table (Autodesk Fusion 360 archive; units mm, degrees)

design "millingcoffeetablefabacd" references "cutting final cnc stool faba acd"
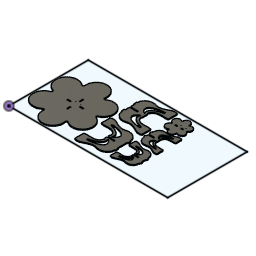
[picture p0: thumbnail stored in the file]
parameter "thickness" = 12 comment "plywood thickness"
parameter "slot1" = 13 comment "sloth dimentione"
parameter "slot2" = 13.2 comment "slot 1"
sketch "shape flower 1meter" plane through (0, 0, 0) normal (0, 0, 1) x axis (1, 0, 0)
  curve K1 (-39.7573, -29.352) -> (-39.7821, -29.352)
  curve K2 (-39.7821, -29.3556) -> (-39.7573, -29.352)
  line L1 (-39.7821, -29.352) -> (-39.7821, -29.3556)
  line L2 (-35.9332, 49.8113) -> (-35.9332, 49.8077)
  curve K3 (-35.838, 49.7971) -> (-35.9332, 49.8113)
  line L3 (308.597, -188.8388) -> (308.8105, -188.7105)
  curve K4 (23.8593, -355.0901) -> (308.597, -188.8388)
  line L4 (23.845, -355.1043) -> (23.8593, -355.0901)
  curve K5 (-14.6061, -354.7911) -> (23.845, -355.1043)
  curve K6 (-303.7587, -199.6903) -> (-14.6061, -354.7911)
  curve K7 (-303.7444, -199.6761) -> (-303.7587, -199.6903)
  curve K8 (-321.3466, -169.9122) -> (-303.7444, -199.6761)
  curve K9 (-329.7916, -170.4675) -> (-329.6918, -170.4675)
  curve K10 (-314.2542, 149.1041) -> (-329.7916, -170.4675)
  line L5 (-314.2542, 149.0898) -> (-314.2542, 149.1041)
  curve K11 (-311.2495, 148.6625) -> (-313.87, 149.047)
  curve K12 (-288.948, 178.2557) -> (-311.2495, 148.6625)
  curve K13 (-18.4511, 342.0005) -> (-288.948, 178.2557)
  line L6 (-18.4226, 342.0148) -> (-18.4511, 342.0005)
  curve K14 (20.242, 342.2854) -> (-18.4226, 342.0148)
  curve K15 (20.2705, 342.328) -> (20.242, 342.2854)
  curve K16 (293.5297, 185.9602) -> (20.2705, 342.328)
  curve K17 (293.5155, 185.9317) -> (293.5297, 185.9602)
  curve K18 (312.9976, 157.4779) -> (293.5155, 185.9317)
  curve K19 (323.3506, -159.9576) -> (312.9976, 157.4779)
  curve K20 (308.8105, -188.7105) -> (323.3506, -159.9576)
  curve K21 (-39.7573, -29.352) -> (-37.6901, -29.2145)
  closed curve K22 centre (-35.8975, 48.3404)
  closed curve K23 centre (-375.539, -219.5003)
  closed curve K24 centre (-314.1102, 143.1665)
  closed curve K25 centre (-51.1145, -41.4983)
extrude "Extrude1" new body sketch "shape flower 1meter" along normal blind 12 (= "thickness") bodies "top"
sketch "legs fab acd 1 meter 46 height" plane through (0, 0, 0) normal (0, 0, 1) x axis (1, 0, 0)
  line L1 (-32.825, -144.3201) -> (34.9534, -144.3201)
  curve K1 (37.0389, -82.2767) -> (-32.825, -144.3201)
  curve K2 (34.9534, -144.3201) -> (37.0389, -82.2767)
  line L2 (-58.3723, -144.3201) -> (-80.7913, -144.3201)
  curve K3 (3.6711, -91.1401) -> (-58.3723, -144.3201)
  curve K4 (-27.6113, -47.3448) -> (3.6711, -91.1401)
  curve K5 (-80.7913, -144.3201) -> (-27.6113, -47.3448)
  curve K6 (79.9971, 179.4525) -> (161.3312, 145.0418)
  curve K7 (132.6558, 269.1286) -> (79.9971, 179.4525)
  line L3 (161.3312, 269.1286) -> (132.6558, 269.1286)
  line L4 (161.3312, 145.0418) -> (161.3312, 269.1286)
  curve K8 (71.9709, 176.8456) -> (-2.064, 83.6941)
  curve K9 (1.5856, 233.6752) -> (71.9709, 176.8456)
  curve K10 (-17.1838, 141.3922) -> (1.5856, 233.6752)
  curve K11 (-2.064, 83.6941) -> (-17.1838, 141.3922)
  curve K12 (47.0854, 262.3992) -> (10.0679, 247.2794)
  line L5 (100.7868, 262.3992) -> (47.0854, 262.3992)
  curve K13 (60.6411, 205.0482) -> (100.7868, 262.3992)
  curve K14 (10.0679, 247.2794) -> (60.6411, 205.0482)
  curve K15 (68.4743, 9.5654) -> (135.0093, 68.3558)
  curve K16 (59.9335, -29.5908) -> (68.4743, 9.5654)
  curve K17 (59.9335, -97.1977) -> (59.9335, -29.5908)
  curve K18 (58.79, -141.8164) -> (59.9335, -97.1977)
  line L6 (58.7898, -141.8113) -> (58.79, -141.8164)
  line L7 (55.6808, -167.4134) -> (58.7898, -141.8113)
  line L8 (-83.214, -167.4134) -> (55.6808, -167.4134)
  curve K19 (-87.1704, -96.1666) -> (-83.214, -167.4134)
  curve K20 (-49.2854, -14.2704) -> (-87.1704, -96.1666)
  curve K21 (-27.4151, 77.7135) -> (-49.2854, -14.2704)
  curve K22 (-30.7897, 102.6214) -> (-27.4151, 77.7135)
  curve K23 (-39.8563, 135.5953) -> (-30.7897, 102.6214)
  curve K24 (11.8482, 271.9936) -> (-39.8563, 135.5953)
  curve K25 (46.7469, 288.6515) -> (11.8482, 271.9936)
  line L9 (195.8212, 288.6515) -> (46.7469, 288.6515)
  line L10 (195.8212, 263.8152) -> (195.8212, 288.6515)
  curve K26 (195.7345, 75.4724) -> (195.8212, 263.8152)
  line L11 (195.7345, 58.9478) -> (195.7345, 75.4724)
  line L12 (147.9989, 58.9478) -> (195.7345, 58.9478)
  curve K27 (135.0093, 68.3558) -> (147.9989, 58.9478)
  curve K28 (-5.7438, -51.5785) -> (-5.8152, -30.5557)
  curve K29 (9.3316, -62.4779) -> (-5.7438, -51.5785)
  curve K30 (18.7965, -36.6002) -> (9.3316, -62.4779)
  curve K31 (43.1071, 29.9194) -> (18.7965, -36.6002)
  curve K32 (81.3903, 84.1408) -> (43.1071, 29.9194)
  curve K33 (161.3312, 92.9063) -> (81.3903, 84.1408)
  curve K34 (86.4903, 153.0394) -> (161.3312, 92.9063)
  curve K35 (-5.8152, -30.5506) -> (86.4903, 153.0394)
  line L13 (-5.8152, -30.5557) -> (-5.8152, -30.5506)
  line L14 (68.2014, 288.6515) -> (118.2014, 288.6515)
  line L15 (68.2014, 300.6515) -> (68.2014, 288.6515)
  line L16 (118.2014, 300.6515) -> (68.2014, 300.6515)
  line L17 (118.2014, 288.6515) -> (118.2014, 300.6515)
  point P50 (118.2014, 288.6515)
  point P51 (68.2014, 288.6515)
  point P52 (68.2014, 300.6515)
  point P53 (118.2014, 300.6515)
  horizontal L14
  vertical L15
  horizontal L16
  vertical L17
  coincident L9 P50
  dimension "d16" distance P51 P52 = 12
  dimension "d17" distance P52 P53 = 50
extrude "Extrude3" new body sketch "legs fab acd 1 meter 46 height" along normal blind 12 (= "thickness") bodies "old legs (1)"
move "Move2"
mirror "Mirror2" mirrorStitchTolerance 0.1
sketch "Sketch4" plane through (0, 8.4468, 0) normal (0, 1, 0) x axis (-1, 0, 0)
  line L1 (-195.8152, -319.9974) -> (-195.8152, -320.0025)
  curve K1 (-103.5097, -136.4075) -> (-195.8152, -319.9974)
  curve K2 (-28.6688, -196.5406) -> (-103.5097, -136.4075)
  curve K3 (-108.6097, -205.3061) -> (-28.6688, -196.5406)
  curve K4 (-146.8929, -259.5274) -> (-108.6097, -205.3061)
  curve K5 (-171.2035, -326.047) -> (-146.8929, -259.5274)
  curve K6 (-180.6684, -351.9248) -> (-171.2035, -326.047)
  curve K7 (-195.7438, -341.0254) -> (-180.6684, -351.9248)
  curve K8 (-195.8152, -320.0025) -> (-195.7438, -341.0254)
  line L2 (-71.7986, -0.7953) -> (71.7986, -0.7953)
  line L3 (-71.7986, 11.2047) -> (-71.7986, -0.7953)
  line L4 (-121.7986, 11.2047) -> (-71.7986, 11.2047)
  line L5 (-121.7986, -0.7953) -> (-121.7986, 11.2047)
  line L6 (-143.2531, -0.7953) -> (-121.7986, -0.7953)
  curve K9 (-143.2531, -0.7953) -> (-178.1518, -17.4533)
  curve K10 (-178.1518, -17.4533) -> (-229.8563, -153.8516)
  curve K11 (-229.8563, -153.8516) -> (-220.7897, -186.8255)
  curve K12 (-220.7897, -186.8255) -> (-217.4151, -211.7333)
  curve K13 (-217.4151, -211.7333) -> (-239.2854, -303.7172)
  curve K14 (-239.2854, -303.7172) -> (-277.1704, -385.6134)
  curve K15 (-277.1704, -385.6134) -> (-273.214, -456.8603)
  line L7 (-134.3192, -456.8603) -> (-273.214, -456.8603)
  line L8 (-131.2102, -431.2581) -> (-134.3192, -456.8603)
  line L9 (-131.21, -431.2633) -> (-131.2102, -431.2581)
  curve K16 (-131.21, -431.2633) -> (-130.0665, -386.6446)
  curve K17 (-130.0665, -386.6446) -> (-130.0665, -319.0377)
  curve K18 (-130.0665, -319.0377) -> (-121.5257, -279.8815)
  curve K19 (-121.5257, -279.8815) -> (-54.9907, -221.091)
  curve K20 (-54.9907, -221.091) -> (-42.0011, -230.4991)
  line L10 (42.0011, -230.4991) -> (-42.0011, -230.4991)
  curve K21 (54.9907, -221.091) -> (42.0011, -230.4991)
  curve K22 (121.5257, -279.8815) -> (54.9907, -221.091)
  curve K23 (130.0665, -319.0377) -> (121.5257, -279.8815)
  curve K24 (130.0665, -386.6446) -> (130.0665, -319.0377)
  curve K25 (131.21, -431.2633) -> (130.0665, -386.6446)
  line L11 (131.2102, -431.2581) -> (131.21, -431.2633)
  line L12 (134.3192, -456.8603) -> (131.2102, -431.2581)
  line L13 (273.214, -456.8603) -> (134.3192, -456.8603)
  curve K26 (277.1704, -385.6134) -> (273.214, -456.8603)
  curve K27 (239.2854, -303.7172) -> (277.1704, -385.6134)
  curve K28 (217.4151, -211.7333) -> (239.2854, -303.7172)
  curve K29 (220.7897, -186.8255) -> (217.4151, -211.7333)
  curve K30 (229.8563, -153.8516) -> (220.7897, -186.8255)
  curve K31 (178.1518, -17.4533) -> (229.8563, -153.8516)
  curve K32 (143.2531, -0.7953) -> (178.1518, -17.4533)
  line L14 (121.7986, -0.7953) -> (143.2531, -0.7953)
  line L15 (121.7986, 11.2047) -> (121.7986, -0.7953)
  line L16 (71.7986, 11.2047) -> (121.7986, 11.2047)
  line L17 (71.7986, -0.7953) -> (71.7986, 11.2047)
  line L18 (195.8152, -320.0025) -> (195.8152, -319.9974)
  curve K33 (195.8152, -320.0025) -> (195.7438, -341.0254)
  curve K34 (195.7438, -341.0254) -> (180.6684, -351.9248)
  curve K35 (180.6684, -351.9248) -> (171.2035, -326.047)
  curve K36 (171.2035, -326.047) -> (146.8929, -259.5274)
  curve K37 (146.8929, -259.5274) -> (108.6097, -205.3061)
  curve K38 (108.6097, -205.3061) -> (28.6688, -196.5406)
  curve K39 (28.6688, -196.5406) -> (103.5097, -136.4075)
  curve K40 (103.5097, -136.4075) -> (195.8152, -319.9974)
  line L19 (6.5, 0) -> (-6.5, 0)
  line L20 (6.5, -120) -> (6.5, 0)
  line L21 (-6.5, -120) -> (6.5, -120)
  line L22 (-6.5, 0) -> (-6.5, -120)
  point P1 (0, 0)
  point P60 (-6.5, 0)
  point P63 (-6.5, -120)
  point P62 (6.5, -120)
  horizontal L19
  vertical L20
  horizontal L21
  vertical L22
  midpoint P1 L19
  dimension "d18" distance P60 P63 = 120
  dimension "d70" distance P62 P63 = 13 (= "slot1")
copy_paste_bodies "CopyPasteBodies2"
move "Move4"
extrude "Extrude4" cut sketch "Sketch4" profile of L2 L20 L21 L22 against normal blind 75
chamfer "Chamfer1" distance 6.5 (= "slot1 / 2")
sketch "legs fab acd" plane through (0, 0, 0) normal (0, 0, 1) x axis (1, 0, 0)
  curve K1 (-42.4639, -297.829) -> (-43.2542, -328.6618)
  curve K2 (-42.4639, -251.1107) -> (-42.4639, -297.829)
  curve K3 (-36.562, -224.0526) -> (-42.4639, -251.1107)
  curve K4 (9.4156, -183.4267) -> (-36.562, -224.0526)
  curve K5 (51.4384, -48.3587) -> (51.3785, -178.509)
  curve K6 (-75.6922, -42.7072) -> (-51.5763, -31.196)
  curve K7 (-111.4216, -136.9623) -> (-75.6922, -42.7072)
  curve K8 (-105.1562, -159.7482) -> (-111.4216, -136.9623)
  curve K9 (-102.8243, -176.9603) -> (-105.1562, -159.7482)
  curve K10 (-117.9374, -240.5238) -> (-102.8243, -176.9603)
  curve K11 (-144.117, -297.1164) -> (-117.9374, -240.5238)
  curve K12 (-141.383, -346.3501) -> (-144.117, -297.1164)
  line L1 (-45.4027, -346.3501) -> (-141.383, -346.3501)
  line L2 (-43.2543, -328.6582) -> (-45.4027, -346.3501)
  line L3 (-43.2542, -328.6618) -> (-43.2543, -328.6582)
  curve K13 (-87.8489, -266.3048) -> (-87.8982, -251.7774)
  curve K14 (-77.4313, -273.8366) -> (-87.8489, -266.3048)
  curve K15 (-70.8908, -255.9543) -> (-77.4313, -273.8366)
  curve K16 (-54.0915, -209.9874) -> (-70.8908, -255.9543)
  curve K17 (-27.6367, -172.5189) -> (-54.0915, -209.9874)
  curve K18 (27.6048, -166.4616) -> (-27.6367, -172.5189)
  curve K19 (-24.1124, -124.9079) -> (27.6048, -166.4616)
  curve K20 (-87.8982, -251.7739) -> (-24.1124, -124.9079)
  line L4 (-87.8982, -251.7774) -> (-87.8982, -251.7739)
  line L5 (51.344, -30.0127) -> (51.4384, -48.3587)
  line L6 (27.6251, -185.9832) -> (37.3593, -185.9832)
  curve K21 (27.6251, -185.9832) -> (9.4156, -183.4267)
  line L7 (51.3785, -186.0408) -> (51.3785, -178.509)
  line L8 (51.3785, -186.0408) -> (37.3593, -185.9832)
  line L9 (-45, -30.0127) -> (51.344, -30.0127)
  line L10 (-33.6745, -30.0127) -> (22.2673, -30.0127)
  line L11 (-33.6745, -18.0127) -> (-33.6745, -30.0127)
  line L12 (22.2673, -18.0127) -> (-33.6745, -18.0127)
  line L13 (22.2673, -30.0127) -> (22.2673, -18.0127)
  curve K22 (-45, -30.0127) -> (-51.5763, -31.196)
  point P34 (22.2673, -30.0127)
  point P35 (-33.6745, -30.0127)
  point P36 (-33.6745, -18.0127)
  horizontal L6
  vertical L7
  horizontal L9
  horizontal L10
  vertical L11
  horizontal L12
  vertical L13
  coincident L9 P34
  dimension "d8" distance P35 P36 = 12
sketch "Sketch5" plane through (6, 0, 0) normal (1, 0, 0) x axis (0, 1, 0)
  line L1 (-193.3684, -319.9974) -> (-193.3684, -320.0025)
  curve K1 (-101.0629, -136.4075) -> (-193.3684, -319.9974)
  curve K2 (-26.2219, -196.5406) -> (-101.0629, -136.4075)
  curve K3 (-106.1629, -205.3061) -> (-26.2219, -196.5406)
  curve K4 (-144.4461, -259.5274) -> (-106.1629, -205.3061)
  curve K5 (-168.7567, -326.047) -> (-144.4461, -259.5274)
  curve K6 (-178.2216, -351.9248) -> (-168.7567, -326.047)
  curve K7 (-193.297, -341.0254) -> (-178.2216, -351.9248)
  curve K8 (-193.3684, -320.0025) -> (-193.297, -341.0254)
  line L2 (-69.3517, -0.7953) -> (74.2454, -0.7953)
  line L3 (-69.3517, 11.2047) -> (-69.3517, -0.7953)
  line L4 (-119.3517, 11.2047) -> (-69.3517, 11.2047)
  line L5 (-119.3517, -0.7953) -> (-119.3517, 11.2047)
  line L6 (-140.8063, -0.7953) -> (-119.3517, -0.7953)
  curve K9 (-140.8063, -0.7953) -> (-175.7049, -17.4533)
  curve K10 (-175.7049, -17.4533) -> (-227.4094, -153.8516)
  curve K11 (-227.4094, -153.8516) -> (-218.3428, -186.8255)
  curve K12 (-218.3428, -186.8255) -> (-214.9682, -211.7333)
  curve K13 (-214.9682, -211.7333) -> (-236.8386, -303.7172)
  curve K14 (-236.8386, -303.7172) -> (-274.7236, -385.6134)
  curve K15 (-274.7236, -385.6134) -> (-270.7672, -456.8603)
  line L7 (-131.8724, -456.8603) -> (-270.7672, -456.8603)
  line L8 (-128.7633, -431.2581) -> (-131.8724, -456.8603)
  line L9 (-128.7632, -431.2633) -> (-128.7633, -431.2581)
  curve K16 (-128.7632, -431.2633) -> (-127.6197, -386.6446)
  curve K17 (-127.6197, -386.6446) -> (-127.6197, -319.0377)
  curve K18 (-127.6197, -319.0377) -> (-119.0788, -279.8815)
  curve K19 (-119.0788, -279.8815) -> (-52.5439, -221.091)
  curve K20 (-52.5439, -221.091) -> (-39.5542, -230.4991)
  line L10 (44.4479, -230.4991) -> (-39.5542, -230.4991)
  curve K21 (57.4376, -221.091) -> (44.4479, -230.4991)
  curve K22 (123.9725, -279.8815) -> (57.4376, -221.091)
  curve K23 (132.5134, -319.0377) -> (123.9725, -279.8815)
  curve K24 (132.5134, -386.6446) -> (132.5134, -319.0377)
  curve K25 (133.6569, -431.2633) -> (132.5134, -386.6446)
  line L11 (133.657, -431.2581) -> (133.6569, -431.2633)
  line L12 (136.7661, -456.8603) -> (133.657, -431.2581)
  line L13 (275.6609, -456.8603) -> (136.7661, -456.8603)
  curve K26 (279.6173, -385.6134) -> (275.6609, -456.8603)
  curve K27 (241.7323, -303.7172) -> (279.6173, -385.6134)
  curve K28 (219.8619, -211.7333) -> (241.7323, -303.7172)
  curve K29 (223.2365, -186.8255) -> (219.8619, -211.7333)
  curve K30 (232.3031, -153.8516) -> (223.2365, -186.8255)
  curve K31 (180.5986, -17.4533) -> (232.3031, -153.8516)
  curve K32 (145.7, -0.7953) -> (180.5986, -17.4533)
  line L14 (124.2454, -0.7953) -> (145.7, -0.7953)
  line L15 (124.2454, 11.2047) -> (124.2454, -0.7953)
  line L16 (74.2454, 11.2047) -> (124.2454, 11.2047)
  line L17 (74.2454, -0.7953) -> (74.2454, 11.2047)
  line L18 (198.2621, -320.0025) -> (198.2621, -319.9974)
  curve K33 (198.2621, -320.0025) -> (198.1907, -341.0254)
  curve K34 (198.1907, -341.0254) -> (183.1153, -351.9248)
  curve K35 (183.1153, -351.9248) -> (173.6504, -326.047)
  curve K36 (173.6504, -326.047) -> (149.3398, -259.5274)
  curve K37 (149.3398, -259.5274) -> (111.0566, -205.3061)
  curve K38 (111.0566, -205.3061) -> (31.1156, -196.5406)
  curve K39 (31.1156, -196.5406) -> (105.9566, -136.4075)
  curve K40 (105.9566, -136.4075) -> (198.2621, -319.9974)
  line L19 (-4.1532, -230.4991) -> (9.0468, -230.4991)
  line L20 (-4.1532, -120.4991) -> (-4.1532, -230.4991)
  line L21 (9.0468, -120.4991) -> (-4.1532, -120.4991)
  line L22 (9.0468, -230.4991) -> (9.0468, -120.4991)
  point P60 (9.0468, -230.4991)
  point P62 (-4.1532, -120.4991)
  point P63 (9.0468, -120.4991)
  point P61 (-4.1532, -230.4991)
  horizontal L19
  vertical L20
  horizontal L21
  vertical L22
  coincident L10 P60
  midpoint L10 L19
  dimension "d22" distance P62 P63 = 13.2 (= "slot2")
  dimension "d23" distance P61 P62 = 110
extrude "Extrude5" cut sketch "Sketch5" profile of L10 L19 L20 L21 L22 against normal blind 90
chamfer "Chamfer2" distance 6.5 (= "slot1 / 2")
extrude "Extrude6" cut of existing geometry blind 50
extrude "Extrude7" cut of existing geometry blind 50 second side blind 50
sketch "Sketch7" plane through (0, 0, 0) normal (0, 0, 1) x axis (1, 0, 0)
  line L1 (-419.7286, 205.8075) -> (-469.7286, 205.8075)
  line L2 (-419.7286, 255.8075) -> (-419.7286, 205.8075)
  line L3 (-469.7286, 255.8075) -> (-419.7286, 255.8075)
  line L4 (-469.7286, 205.8075) -> (-469.7286, 255.8075)
  line L5 (-438.2286, 230.8075) -> (-451.2286, 230.8075)
  line L6 (-438.2286, 205.8075) -> (-438.2286, 230.8075)
  line L7 (-451.2286, 205.8075) -> (-438.2286, 205.8075)
  line L8 (-451.2286, 230.8075) -> (-451.2286, 205.8075)
  point P2 (-469.7286, 205.8075)
  point P5 (-469.7286, 255.8075)
  point P4 (-419.7286, 255.8075)
  point P6 (-451.2286, 230.8075)
  point P7 (-438.2286, 230.8075)
  point P9 (-451.2286, 205.8075)
  horizontal L1
  vertical L2
  horizontal L3
  vertical L4
  horizontal L5
  vertical L6
  horizontal L7
  vertical L8
  midpoint L1 L7
  dimension "d48" distance P2 P5 = 50
  dimension "d49" distance P4 P5 = 50
  dimension "d52" distance P6 P7 = 13 (= "slot1")
  dimension "d53" distance P6 P9 = 25
extrude "Extrude8" new body sketch "Sketch7" profile of L1 L2 L3 L4 L5 L6 L8 along normal blind 12 (= "thickness")
chamfer "Chamfer3" distance 6.5 (= "slot1 / 2")
sketch "Sketch6" plane through (0, 0, 0) normal (0, 0, 1) x axis (1, 0, 0)
  line L1 (2438.4, 0) -> (0, 0)
  line L2 (2438.4, 1219.2) -> (2438.4, 0)
  line L3 (0, 1219.2) -> (2438.4, 1219.2)
  line L4 (0, 0) -> (0, 1219.2)
  point P1 (0, 0)
  point P2 (0, 0)
  point P5 (0, 1219.2)
  point P3 (2438.4, 0)
  horizontal L1
  vertical L2
  horizontal L3
  vertical L4
  coincident P1 P2
  dimension "d33" distance P2 P5 = 1219.2 (= "4 ft")
  dimension "d34" distance P2 P3 = 2438.4 (= "8 ft")
component_from_bodies "Body->Comp1"
component_from_bodies "Body->Comp2"
component_from_bodies "Body->Comp3"
step "Arrange" sketch "Sketch6" AngleFromX 0 Priority 500 AngleFromX 0 Priority 500 AngleFromX 0 Priority 500 originOffsetX 0 originOffsetY 0 grainDirection 0 objectSpacing 6.35 frameWidth 10 placementClearance 10
component_from_bodies "Body->Comp4"
move "Move1"
move "Move1"
move "Move2"
move "Move2"
position "Position1"
extrude "Extrude9" new body sketch "Sketch7" profile of L1 L2 L3 L4 L5 L6 L8 along normal blind 12 (= "thickness")
chamfer "Chamfer4" distance 6.5 (= "slot1 / 2")
copy_paste_bodies "CopyPasteBodies4"
move "Move6"
move "Move7"
sketch "Sketch8" plane through (-15, -150.0001, 22) normal (0, 0, 1) x axis (-1, 0, 0)
  line L1 (-573.157, -669.1254) -> (-573.157, -657.1254)
  line L2 (-623.157, -669.1254) -> (-573.157, -669.1254)
  line L3 (-623.157, -657.1254) -> (-623.157, -669.1254)
  line L4 (-573.157, -657.1254) -> (-623.157, -657.1254)
  line L5 (-379.5599, -669.1254) -> (-379.5599, -657.1254)
  line L6 (-429.5599, -669.1254) -> (-379.5599, -669.1254)
  line L7 (-429.5599, -657.1254) -> (-429.5599, -669.1254)
  line L8 (-379.5599, -657.1254) -> (-429.5599, -657.1254)
  line L9 (-495.3584, -541.3268) -> (-507.3584, -541.3268)
  line L10 (-495.3584, -591.3268) -> (-495.3584, -541.3268)
  line L11 (-507.3584, -591.3268) -> (-495.3584, -591.3268)
  line L12 (-507.3584, -541.3268) -> (-507.3584, -591.3268)
  line L13 (-495.3584, -734.924) -> (-507.3584, -734.924)
  line L14 (-495.3584, -784.924) -> (-495.3584, -734.924)
  line L15 (-507.3584, -784.924) -> (-495.3584, -784.924)
  line L16 (-507.3584, -734.924) -> (-507.3584, -784.924)
  curve K1 (-548.7189, -699.0388) -> (-548.7087, -698.9635)
  line L17 (-548.7229, -699.0586) -> (-548.7193, -699.0586)
  curve K2 (-548.7189, -699.0388) -> (-548.7229, -699.0586)
  curve K3 (-469.5596, -702.8828) -> (-469.6971, -700.8155)
  curve K4 (-469.5566, -702.9017) -> (-469.5596, -702.8828)
  curve K5 (-469.556, -702.9075) -> (-469.5566, -702.9017)
  line L18 (-469.5596, -702.9075) -> (-469.556, -702.9075)
  curve K6 (-469.5566, -702.9017) -> (-469.5596, -702.9075)
  curve K7 (-469.5596, -702.8828) -> (-469.5566, -702.9017)
  line L19 (-648.0157, -977.3797) -> (-648.0014, -977.3797)
  curve K8 (-328.4441, -992.917) -> (-648.0157, -977.3797)
  curve K9 (-328.4441, -992.8172) -> (-328.4441, -992.917)
  curve K10 (-299.2355, -966.8698) -> (-328.9994, -984.4721)
  curve K11 (-299.2212, -966.8841) -> (-299.2355, -966.8698)
  curve K12 (-144.1205, -677.7315) -> (-299.2212, -966.8841)
  curve K13 (-143.8073, -639.2804) -> (-144.1205, -677.7315)
  line L20 (-143.8215, -639.2661) -> (-143.8073, -639.2804)
  curve K14 (-310.0728, -354.5284) -> (-143.8215, -639.2661)
  line L21 (-310.2011, -354.315) -> (-310.0728, -354.5284)
  curve K15 (-338.9539, -339.7748) -> (-310.2011, -354.315)
  curve K16 (-656.3895, -350.1278) -> (-338.9539, -339.7748)
  curve K17 (-684.8433, -369.61) -> (-656.3895, -350.1278)
  curve K18 (-684.8718, -369.5957) -> (-684.8433, -369.61)
  curve K19 (-841.2396, -642.8549) -> (-684.8718, -369.5957)
  curve K20 (-841.197, -642.8834) -> (-841.2396, -642.8549)
  curve K21 (-840.9264, -681.548) -> (-841.197, -642.8834)
  line L22 (-840.9121, -681.5766) -> (-840.9264, -681.548)
  curve K22 (-677.1673, -952.0734) -> (-840.9121, -681.5766)
  curve K23 (-647.5741, -974.375) -> (-677.1673, -952.0734)
  curve K24 (-647.9586, -976.9955) -> (-647.5741, -974.375)
  line L23 (-507.1584, -735.124) -> (-507.1584, -784.724)
  line L24 (-495.5584, -735.124) -> (-507.1584, -735.124)
  line L25 (-495.5584, -784.724) -> (-495.5584, -735.124)
  line L26 (-507.1584, -784.724) -> (-495.5584, -784.724)
  line L27 (-622.957, -668.9254) -> (-573.357, -668.9254)
  line L28 (-622.957, -657.3254) -> (-622.957, -668.9254)
  line L29 (-573.357, -657.3254) -> (-622.957, -657.3254)
  line L30 (-573.357, -668.9254) -> (-573.357, -657.3254)
  line L31 (-495.5584, -591.1268) -> (-495.5584, -541.5268)
  line L32 (-507.1584, -591.1268) -> (-495.5584, -591.1268)
  line L33 (-507.1584, -541.5268) -> (-507.1584, -591.1268)
  line L34 (-495.5584, -541.5268) -> (-507.1584, -541.5268)
  line L35 (-429.3599, -668.9254) -> (-379.7599, -668.9254)
  line L36 (-429.3599, -657.3254) -> (-429.3599, -668.9254)
  line L37 (-379.7599, -657.3254) -> (-429.3599, -657.3254)
  line L38 (-379.7599, -668.9254) -> (-379.7599, -657.3254)
  closed curve K25 centre (-547.252, -699.0229)
  closed curve K26 centre (-547.252, -699.0229)
  closed curve K27 centre (-457.4133, -714.2399)
  closed curve K28 centre (-642.0781, -977.2356)
  closed curve K29 centre (-279.4113, -1038.6645)
  dimension "d71" = 0.2
  dimension "d72" = 0.2
  dimension "d73" = 0.2
  dimension "d74" = 0.2
component_insert "Component Insert"
move "Move3"
move "Move3"
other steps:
base_feature "Base Feature1" bodies "old legs (1)"
move "Move1"
base_feature "Base Feature1"
base_feature "Base Feature1" bodies "old legs (1) (1)"
base_feature "Base Feature1" bodies "top"
base_feature "Base Feature2" bodies "old legs (1)", "old legs (1) (1)"
base_feature "Base Feature4"
create_component "CreateComponent1"
remove_body "RemoveBody1"
create_component "CreateComponent2"
remove_body "RemoveBody2"
create_component "CreateComponent3"
remove_body "RemoveBody3"
create_component "CreateComponent4"
create_component "CreateComponent1"
create_component "CreateComponent5"
remove_body "RemoveBody4"
named bodies: "top", "old legs (1)", "old legs (1) (1)"

design "cutting final cnc stool faba acd"
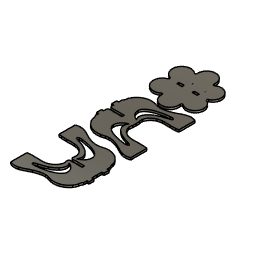
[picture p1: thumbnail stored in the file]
parameter "thickness" = 12 comment "plywood thickness"
parameter "slot1" = 13 comment "slot size"
parameter "slot2" = 13.2
sketch "Sketch5" plane through (0, 0, 0) normal (0, 0, 1) x axis (1, 0, 0)
extrude "Extrude4" new body sketch "Sketch5" along normal blind 12 (= "thickness") bodies "test"
chamfer "Chamfer1" distance 6.5 (= "slot1 / 2")
sketch "Sketch4" plane through (0, 0, 0) normal (0, 0, 1) x axis (1, 0, 0)
  curve K1 (-41.7573, -14.352) -> (-41.7821, -14.352)
  curve K2 (-41.7821, -14.3556) -> (-41.7573, -14.352)
  line L1 (-41.7821, -14.352) -> (-41.7821, -14.3556)
  line L2 (-37.9332, 64.8113) -> (-37.9332, 64.8077)
  curve K3 (-37.838, 64.7971) -> (-37.9332, 64.8113)
  line L3 (101.2479, -58.1626) -> (101.3179, -58.1205)
  curve K4 (7.8268, -112.7089) -> (101.2479, -58.1626)
  line L4 (7.8221, -112.7136) -> (7.8268, -112.7089)
  curve K5 (-4.7936, -112.6108) -> (7.8221, -112.7136)
  curve K6 (-99.6632, -61.723) -> (-4.7936, -112.6108)
  curve K7 (-99.6585, -61.7183) -> (-99.6632, -61.723)
  curve K8 (-105.4337, -51.9529) -> (-99.6585, -61.7183)
  curve K9 (-108.2045, -52.1351) -> (-108.1717, -52.1351)
  curve K10 (-103.1067, 52.7149) -> (-108.2045, -52.1351)
  line L5 (-103.1067, 52.7102) -> (-103.1067, 52.7149)
  curve K11 (-102.1209, 52.57) -> (-102.9807, 52.6962)
  curve K12 (-94.8039, 62.2794) -> (-102.1209, 52.57)
  curve K13 (-6.0551, 116.0033) -> (-94.8039, 62.2794)
  line L6 (-6.0457, 116.008) -> (-6.0551, 116.0033)
  curve K14 (6.6399, 116.0968) -> (-6.0457, 116.008)
  curve K15 (6.6493, 116.1108) -> (6.6399, 116.0968)
  curve K16 (96.3044, 64.8072) -> (6.6493, 116.1108)
  curve K17 (96.2997, 64.7979) -> (96.3044, 64.8072)
  curve K18 (102.6917, 55.4623) -> (96.2997, 64.7979)
  curve K19 (106.0885, -48.6868) -> (102.6917, 55.4623)
  curve K20 (101.3179, -58.1205) -> (106.0885, -48.6868)
  curve K21 (-41.7573, -14.352) -> (-39.6901, -14.2145)
  closed curve K22 centre (-37.8975, 63.3404)
  closed curve K23 centre (-123.214, -68.2225)
  closed curve K24 centre (-103.0595, 50.7668)
  closed curve K25 centre (-53.1145, -26.4983)
extrude "Extrude3" new body sketch "Sketch4" along normal blind 12 (= "thickness") bodies "FINAL top"
sketch "Sketch6" plane through (0, 0, 0) normal (0, 1, 0) x axis (1, 0, 0)
  curve K1 (92.5364, 295.6076) -> (93.3267, 326.4404)
  curve K2 (92.5363, 248.8892) -> (92.5364, 295.6076)
  curve K3 (86.6343, 221.8312) -> (92.5363, 248.8892)
  curve K4 (40.6567, 181.2054) -> (86.6343, 221.8312)
  curve K5 (-1.3592, 46.1379) -> (-1.3054, 176.2882)
  curve K6 (125.5806, 40.4977) -> (101.4728, 28.9695)
  curve K7 (161.4384, 134.7041) -> (125.5806, 40.4977)
  curve K8 (155.1788, 157.4916) -> (161.4384, 134.7041)
  curve K9 (152.849, 174.7039) -> (155.1788, 157.4916)
  curve K10 (167.972, 238.265) -> (152.849, 174.7039)
  curve K11 (194.1536, 294.8568) -> (167.972, 238.265)
  curve K12 (191.4202, 344.0905) -> (194.1536, 294.8568)
  line L1 (95.4731, 344.1109) -> (191.4202, 344.0905)
  line L2 (93.3267, 326.4366) -> (95.4731, 344.1109)
  line L3 (93.3267, 326.4404) -> (93.3267, 326.4366)
  curve K13 (137.921, 264.0835) -> (137.9703, 249.5561)
  curve K14 (127.5034, 271.6153) -> (137.921, 264.0835)
  curve K15 (120.9629, 253.733) -> (127.5034, 271.6153)
  curve K16 (104.1636, 207.7661) -> (120.9629, 253.733)
  curve K17 (77.7088, 170.2975) -> (104.1636, 207.7661)
  curve K18 (22.4673, 164.2403) -> (77.7088, 170.2975)
  curve K19 (74.1845, 122.6866) -> (22.4673, 164.2403)
  curve K20 (137.9703, 249.5526) -> (74.1845, 122.6866)
  line L4 (137.9703, 249.5561) -> (137.9703, 249.5526)
  line L5 (-1.3054, 183.8196) -> (19.6106, 183.8195)
  line L6 (-1.3054, 176.2882) -> (-1.3054, 183.8196)
  line L7 (-1.3615, 26.7173) -> (-1.3592, 46.1379)
  line L8 (-1.3615, 26.7173) -> (-1.3622, 20.3)
  line L9 (60, 8.4) -> (30, 8.4)
  line L10 (60, 20.4) -> (60, 8.4)
  line L11 (30, 20.4) -> (60, 20.4)
  line L12 (30, 8.4) -> (30, 20.4)
  line L13 (30, 20.4) -> (-1.3622, 20.3)
  line L14 (30, 20.4) -> (60, 20.4)
  line L15 (60, 20.4) -> (79, 20.4)
  curve K21 (79, 20.4) -> (101.4728, 28.9695)
  curve K22 (19.6106, 183.8195) -> (40.6567, 181.2054)
  point P32 (30, 8.4)
  point P35 (30, 20.4)
  perpendicular L5 L6
  horizontal L9
  vertical L10
  horizontal L11
  vertical L12
  perpendicular L10 L14
  horizontal L15
  dimension "d46" distance P32 P35 = 12 (= "thickness")
extrude "Extrude10" new body sketch "Sketch6" profile of K1 K2 K3 K4 K5 K6 K7 K8 K9 K10 K11 K12 L1 L2 L3 K13 K14 K15 K16 K17 K18 K19 K20 L4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 along normal blind 12 (= "thickness")
mirror "Mirror2" mirrorStitchTolerance 0.1
copy_paste_bodies "CopyPasteBodies4"
move "Move9"
sketch "Sketch12" plane through (10.2776, 0, 0.0328) normal (1, 0, 0.0032) x axis (0, 1, 0)
  line L1 (-131.0433, -249.1112) -> (-131.0433, -249.1147)
  curve K1 (-66.8532, -122.4494) -> (-131.0433, -249.1112)
  curve K2 (-15.2687, -164.1678) -> (-66.8532, -122.4494)
  curve K3 (-70.5293, -170.0488) -> (-15.2687, -164.1678)
  curve K4 (-97.1035, -207.4327) -> (-70.5293, -170.0488)
  curve K5 (-114.0493, -253.3459) -> (-97.1035, -207.4327)
  curve K6 (-120.6469, -271.2072) -> (-114.0493, -253.3459)
  curve K7 (-131.0403, -263.6422) -> (-120.6469, -271.2072)
  curve K8 (-131.0433, -249.1147) -> (-131.0403, -263.6422)
  line L2 (144.8959, -249.995) -> (144.8959, -249.9914)
  curve K9 (144.8959, -249.995) -> (144.8002, -264.5221)
  curve K10 (144.8002, -264.5221) -> (134.3587, -272.0207)
  curve K11 (134.3587, -272.0207) -> (127.8753, -254.1176)
  curve K12 (127.8753, -254.1176) -> (111.2227, -208.0973)
  curve K13 (111.2227, -208.0973) -> (84.8875, -170.5446)
  curve K14 (84.8875, -170.5446) -> (29.6656, -164.3112)
  curve K15 (29.6656, -164.3112) -> (81.5152, -122.9227)
  curve K16 (81.5152, -122.9227) -> (144.8959, -249.9914)
  line L3 (6.2954, -20.2955) -> (7.6576, -20.3042)
  line L4 (6.2954, -20.3042) -> (6.2954, -20.2955)
  line L5 (-22.3425, -20.3042) -> (6.2954, -20.3042)
  line L6 (-22.3043, -8.3043) -> (-22.3425, -20.3042)
  line L7 (-52.3041, -8.2086) -> (-22.3043, -8.3043)
  line L8 (-52.3424, -20.2085) -> (-52.3041, -8.2086)
  line L9 (-71.3423, -20.1479) -> (-52.3424, -20.2085)
  curve K17 (-71.3423, -20.1479) -> (-93.8423, -28.6457)
  curve K18 (-117.9868, -40.0969) -> (-93.8423, -28.6457)
  curve K19 (-154.1449, -134.1884) -> (-117.9868, -40.0969)
  curve K20 (-147.958, -156.9958) -> (-154.1449, -134.1884)
  curve K21 (-145.6831, -174.2154) -> (-147.958, -156.9958)
  curve K22 (-161.0088, -237.728) -> (-145.6831, -174.2154)
  curve K23 (-187.3708, -294.2359) -> (-161.0088, -237.728)
  curve K24 (-184.7945, -343.4781) -> (-187.3708, -294.2359)
  line L10 (-88.8479, -343.8046) -> (-184.7945, -343.4781)
  line L11 (-86.6452, -326.1373) -> (-88.8479, -343.8046)
  line L12 (-86.6451, -326.141) -> (-86.6452, -326.1373)
  curve K25 (-85.7565, -295.3109) -> (-86.6451, -326.141)
  curve K26 (-85.6074, -248.5928) -> (-85.7565, -295.3109)
  curve K27 (-79.6191, -221.5537) -> (-85.6074, -248.5928)
  curve K28 (-33.5122, -181.0748) -> (-79.6191, -221.5537)
  line L13 (5.8306, -183.8145) -> (-12.4745, -183.756)
  line L14 (5.8306, -183.8145) -> (5.8306, -183.8145)
  line L15 (7.136, -183.8186) -> (5.8306, -183.8145)
  line L16 (8.4414, -183.8228) -> (7.136, -183.8186)
  line L17 (8.4414, -183.8228) -> (8.4414, -183.8228)
  curve K29 (47.8008, -181.3341) -> (93.6486, -222.1064)
  curve K30 (93.6486, -222.1064) -> (99.4643, -249.1832)
  curve K31 (99.4643, -249.1832) -> (99.3153, -295.9013)
  curve K32 (99.3153, -295.9013) -> (100.0072, -326.7364)
  line L18 (100.0073, -326.7327) -> (100.0072, -326.7364)
  line L19 (102.0973, -344.4137) -> (100.0073, -326.7327)
  line L20 (198.0439, -344.6993) -> (102.0973, -344.4137)
  curve K33 (198.0439, -344.6993) -> (200.9344, -295.4746)
  curve K34 (200.9344, -295.4746) -> (174.9334, -238.7997)
  curve K35 (174.9334, -238.7997) -> (160.0133, -175.1906)
  curve K36 (160.0133, -175.1906) -> (162.398, -157.9858)
  curve K37 (162.398, -157.9858) -> (168.7303, -135.2184)
  curve K38 (168.7303, -135.2184) -> (133.1731, -40.8981)
  curve K39 (133.1731, -40.8981) -> (109.1023, -29.2931)
  curve K40 (86.6569, -20.6519) -> (109.1023, -29.2931)
  line L21 (67.657, -20.5913) -> (86.6569, -20.6519)
  line L22 (67.6953, -8.5914) -> (67.657, -20.5913)
  line L23 (37.6954, -8.4957) -> (67.6953, -8.5914)
  line L24 (37.6571, -20.4956) -> (37.6954, -8.4957)
  line L25 (9.0198, -20.3129) -> (37.6571, -20.4956)
  line L26 (9.0199, -20.3042) -> (9.0198, -20.3129)
  line L27 (7.6576, -20.3042) -> (9.0199, -20.3042)
  curve K41 (-12.4745, -183.756) -> (-33.5122, -181.0748)
  line L28 (26.7465, -183.8811) -> (8.4414, -183.8228)
  curve K42 (26.7465, -183.8811) -> (47.8008, -181.3341)
  line L29 (-0.7694, -184.8145) -> (12.4306, -184.8145)
  line L30 (-0.7694, -104.8145) -> (-0.7694, -184.8145)
  line L31 (12.4306, -104.8145) -> (-0.7694, -104.8145)
  line L32 (12.4306, -184.8145) -> (12.4306, -104.8145)
  point P72 (12.4306, -184.8145)
  point P73 (-0.7694, -184.8145)
  point P74 (-0.7694, -104.8145)
  horizontal L29
  vertical L30
  horizontal L31
  vertical L32
  dimension "d94" distance P72 P73 = 13.2 (= "slot2")
  dimension "d95" distance P73 P74 = 80
extrude "Extrude19" new body sketch "Sketch12" profile of L1 K1 K2 K3 K4 K5 K6 K7 K8 L2 K9 K10 K11 K12 K13 K14 K15 K16 L3 L4 L5 L6 L7 L8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 along normal blind 12 (= "thickness") bodies "FINAL LEG 1"
chamfer "Chamfer7" distance 6.6 (= "slot2 / 2")
extrude "Extrude12" cut sketch "Sketch12" profile of L13 L14 L15 against normal blind 110
sketch "Sketch11" plane through (0, 0, 0) normal (0, -1, 0) x axis (1, 0, 0)
  line L1 (-137.9703, -249.5526) -> (-137.9703, -249.5561)
  curve K1 (-74.1845, -122.6866) -> (-137.9703, -249.5526)
  curve K2 (-22.4673, -164.2403) -> (-74.1845, -122.6866)
  curve K3 (-77.7088, -170.2975) -> (-22.4673, -164.2403)
  curve K4 (-104.1636, -207.7661) -> (-77.7088, -170.2975)
  curve K5 (-120.9629, -253.733) -> (-104.1636, -207.7661)
  curve K6 (-127.5034, -271.6153) -> (-120.9629, -253.733)
  curve K7 (-137.921, -264.0835) -> (-127.5034, -271.6153)
  curve K8 (-137.9703, -249.5561) -> (-137.921, -264.0835)
  line L2 (137.9703, -249.5561) -> (137.9703, -249.5526)
  curve K9 (137.9703, -249.5561) -> (137.921, -264.0835)
  curve K10 (137.921, -264.0835) -> (127.5034, -271.6153)
  curve K11 (127.5034, -271.6153) -> (120.9629, -253.733)
  curve K12 (120.9629, -253.733) -> (104.1636, -207.7661)
  curve K13 (104.1636, -207.7661) -> (77.7088, -170.2975)
  curve K14 (77.7088, -170.2975) -> (22.4673, -164.2403)
  curve K15 (22.4673, -164.2403) -> (74.1845, -122.6866)
  curve K16 (74.1845, -122.6866) -> (137.9703, -249.5526)
  line L3 (-1.3622, -20.3) -> (0, -20.3043)
  line L4 (-1.3622, -20.3086) -> (-1.3622, -20.3)
  line L5 (-30, -20.4) -> (-1.3622, -20.3086)
  line L6 (-30, -8.4) -> (-30, -20.4)
  line L7 (-60, -8.4) -> (-30, -8.4)
  line L8 (-60, -20.4) -> (-60, -8.4)
  line L9 (-79, -20.4) -> (-60, -20.4)
  curve K17 (-79, -20.4) -> (-101.4728, -28.9695)
  curve K18 (-125.5806, -40.4977) -> (-101.4728, -28.9695)
  curve K19 (-161.4384, -134.7041) -> (-125.5806, -40.4977)
  curve K20 (-155.1788, -157.4916) -> (-161.4384, -134.7041)
  curve K21 (-152.849, -174.7039) -> (-155.1788, -157.4916)
  curve K22 (-167.972, -238.265) -> (-152.849, -174.7039)
  curve K23 (-194.1536, -294.8568) -> (-167.972, -238.265)
  curve K24 (-191.4202, -344.0905) -> (-194.1536, -294.8568)
  line L10 (-95.4731, -344.1109) -> (-191.4202, -344.0905)
  line L11 (-93.3267, -326.4366) -> (-95.4731, -344.1109)
  line L12 (-93.3267, -326.4404) -> (-93.3267, -326.4366)
  curve K25 (-92.5364, -295.6076) -> (-93.3267, -326.4404)
  curve K26 (-92.5363, -248.8892) -> (-92.5364, -295.6076)
  curve K27 (-86.6343, -221.8312) -> (-92.5363, -248.8892)
  curve K28 (-40.6567, -181.2054) -> (-86.6343, -221.8312)
  line L13 (-1.3054, -183.8196) -> (-19.6106, -183.8195)
  line L14 (-1.3054, -183.8196) -> (-1.3054, -183.8196)
  line L15 (0, -183.8196) -> (-1.3054, -183.8196)
  line L16 (1.3054, -183.8196) -> (0, -183.8196)
  line L17 (1.3054, -183.8196) -> (1.3054, -183.8196)
  curve K29 (40.6567, -181.2054) -> (86.6343, -221.8312)
  curve K30 (86.6343, -221.8312) -> (92.5363, -248.8892)
  curve K31 (92.5363, -248.8892) -> (92.5364, -295.6076)
  curve K32 (92.5364, -295.6076) -> (93.3267, -326.4404)
  line L18 (93.3267, -326.4366) -> (93.3267, -326.4404)
  line L19 (95.4731, -344.1109) -> (93.3267, -326.4366)
  line L20 (191.4202, -344.0905) -> (95.4731, -344.1109)
  curve K33 (191.4202, -344.0905) -> (194.1536, -294.8568)
  curve K34 (194.1536, -294.8568) -> (167.972, -238.265)
  curve K35 (167.972, -238.265) -> (152.849, -174.7039)
  curve K36 (152.849, -174.7039) -> (155.1788, -157.4916)
  curve K37 (155.1788, -157.4916) -> (161.4384, -134.7041)
  curve K38 (161.4384, -134.7041) -> (125.5806, -40.4977)
  curve K39 (125.5806, -40.4977) -> (101.4728, -28.9695)
  curve K40 (79, -20.4) -> (101.4728, -28.9695)
  line L21 (60, -20.4) -> (79, -20.4)
  line L22 (60, -8.4) -> (60, -20.4)
  line L23 (30, -8.4) -> (60, -8.4)
  line L24 (30, -20.4) -> (30, -8.4)
  line L25 (1.3622, -20.3086) -> (30, -20.4)
  line L26 (1.3622, -20.3) -> (1.3622, -20.3086)
  line L27 (0, -20.3043) -> (1.3622, -20.3)
  line L28 (5.1378, -20.3) -> (-7.8622, -20.3)
  line L29 (5.1378, -105.3) -> (5.1378, -20.3)
  line L30 (-7.8622, -105.3) -> (5.1378, -105.3)
  line L31 (-7.8622, -20.3) -> (-7.8622, -105.3)
  curve K41 (-19.6106, -183.8195) -> (-40.6567, -181.2054)
  line L32 (19.6106, -183.8195) -> (1.3054, -183.8196)
  curve K42 (19.6106, -183.8195) -> (40.6567, -181.2054)
  point P21 (-1.3622, -20.3)
  point P71 (-7.8622, -20.3)
  point P74 (-7.8622, -105.3)
  point P73 (5.1378, -105.3)
  vertical L29
  horizontal L30
  vertical L31
  midpoint P21 L28
  dimension "d55" distance P71 P74 = 85
  dimension "d93" distance P73 P74 = 13 (= "slot1")
extrude "Extrude20" new body sketch "Sketch11" profile of L1 K1 K2 K3 K4 K5 K6 K7 K8 L2 K9 K10 K11 K12 K13 K14 K15 K16 L5 L6 L7 L8 L9 K17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 along normal blind 12 (= "thickness") bodies "FINAL LEG 2"
chamfer "Chamfer8" distance 6.5 (= "slot1 / 2")
extrude "Extrude11" cut sketch "Sketch11" profile of L3 L4 L5 L25 L26 L27 L29 L30 L31 against normal blind 30
copy_paste_bodies "CopyPasteBodies3"
chamfer "Chamfer5" distance 6.5 (= "slot1 / 2")
move "Move10"
move "Move15"
move "Move16"
move "Move17"
sketch "Sketch14" plane through (0, -9, 0) normal (0, -1, 0) x axis (1, 0, 0)
  line L1 (-14.1243, -21.2798) -> (-7.6243, -27.7591)
  line L2 (-29.7621, -21.3297) -> (-14.1243, -21.2798)
  line L3 (-29.7621, -9.3297) -> (-29.7621, -21.3297)
  line L4 (-59.7621, -9.3297) -> (-29.7621, -9.3297)
  line L5 (-59.7621, -21.3297) -> (-59.7621, -9.3297)
  line L6 (-78.7621, -21.3297) -> (-59.7621, -21.3297)
  curve K1 (-78.7621, -21.3297) -> (-101.2349, -29.8992)
  curve K2 (-125.3427, -41.4275) -> (-101.2349, -29.8992)
  curve K3 (-161.2005, -135.6338) -> (-125.3427, -41.4275)
  curve K4 (-154.9409, -158.4213) -> (-161.2005, -135.6338)
  curve K5 (-152.6111, -175.6336) -> (-154.9409, -158.4213)
  curve K6 (-167.7341, -239.1948) -> (-152.6111, -175.6336)
  curve K7 (-193.9157, -295.7865) -> (-167.7341, -239.1948)
  curve K8 (-191.1823, -345.0202) -> (-193.9157, -295.7865)
  line L7 (-95.2352, -345.0406) -> (-191.1823, -345.0202)
  line L8 (-93.0888, -327.3664) -> (-95.2352, -345.0406)
  line L9 (-93.0888, -327.3701) -> (-93.0888, -327.3664)
  curve K9 (-92.2985, -296.5373) -> (-93.0888, -327.3701)
  curve K10 (-92.2984, -249.8189) -> (-92.2985, -296.5373)
  curve K11 (-86.3964, -222.7609) -> (-92.2984, -249.8189)
  curve K12 (-40.4188, -182.1351) -> (-86.3964, -222.7609)
  curve K13 (-19.3727, -184.7492) -> (-40.4188, -182.1351)
  line L10 (-1.0675, -184.7493) -> (-19.3727, -184.7492)
  line L11 (-1.0675, -184.7493) -> (-1.0675, -184.7493)
  line L12 (0.2379, -184.7493) -> (-1.0675, -184.7493)
  line L13 (1.5433, -184.7493) -> (0.2379, -184.7493)
  line L14 (1.5433, -184.7493) -> (1.5433, -184.7493)
  line L15 (19.8485, -184.7492) -> (1.5433, -184.7493)
  curve K14 (19.8485, -184.7492) -> (40.8946, -182.1351)
  curve K15 (40.8946, -182.1351) -> (86.8722, -222.7609)
  curve K16 (86.8722, -222.7609) -> (92.7742, -249.8189)
  curve K17 (92.7742, -249.8189) -> (92.7743, -296.5373)
  curve K18 (92.7743, -296.5373) -> (93.5646, -327.3701)
  line L16 (93.5646, -327.3664) -> (93.5646, -327.3701)
  line L17 (95.711, -345.0406) -> (93.5646, -327.3664)
  line L18 (191.6581, -345.0202) -> (95.711, -345.0406)
  curve K19 (191.6581, -345.0202) -> (194.3915, -295.7865)
  curve K20 (194.3915, -295.7865) -> (168.2099, -239.1948)
  curve K21 (168.2099, -239.1948) -> (153.0869, -175.6336)
  curve K22 (153.0869, -175.6336) -> (155.4167, -158.4213)
  curve K23 (155.4167, -158.4213) -> (161.6763, -135.6338)
  curve K24 (161.6763, -135.6338) -> (125.8185, -41.4275)
  curve K25 (125.8185, -41.4275) -> (101.7107, -29.8992)
  curve K26 (79.2379, -21.3297) -> (101.7107, -29.8992)
  line L19 (60.2379, -21.3297) -> (79.2379, -21.3297)
  line L20 (60.2379, -9.3297) -> (60.2379, -21.3297)
  line L21 (30.2379, -9.3297) -> (60.2379, -9.3297)
  line L22 (30.2379, -21.3297) -> (30.2379, -9.3297)
  line L23 (11.8756, -21.2711) -> (30.2379, -21.3297)
  line L24 (5.3757, -27.7504) -> (11.8756, -21.2711)
  line L25 (5.3757, -106.2297) -> (5.3757, -27.7504)
  line L26 (-7.6243, -106.2297) -> (5.3757, -106.2297)
  line L27 (-7.6243, -27.7591) -> (-7.6243, -106.2297)
  line L28 (-137.7324, -250.4823) -> (-137.7324, -250.4858)
  curve K27 (-73.9466, -123.6163) -> (-137.7324, -250.4823)
  curve K28 (-22.2294, -165.17) -> (-73.9466, -123.6163)
  curve K29 (-77.4709, -171.2273) -> (-22.2294, -165.17)
  curve K30 (-103.9257, -208.6958) -> (-77.4709, -171.2273)
  curve K31 (-120.725, -254.6627) -> (-103.9257, -208.6958)
  curve K32 (-127.2655, -272.545) -> (-120.725, -254.6627)
  curve K33 (-137.6831, -265.0132) -> (-127.2655, -272.545)
  curve K34 (-137.7324, -250.4858) -> (-137.6831, -265.0132)
  line L29 (138.2082, -250.4858) -> (138.2082, -250.4823)
  curve K35 (138.2082, -250.4858) -> (138.1589, -265.0132)
  curve K36 (138.1589, -265.0132) -> (127.7413, -272.545)
  curve K37 (127.7413, -272.545) -> (121.2008, -254.6627)
  curve K38 (121.2008, -254.6627) -> (104.4015, -208.6958)
  curve K39 (104.4015, -208.6958) -> (77.9467, -171.2273)
  curve K40 (77.9467, -171.2273) -> (22.7052, -165.17)
  curve K41 (22.7052, -165.17) -> (74.4224, -123.6163)
  curve K42 (74.4224, -123.6163) -> (138.2082, -250.4823)
  line L30 (-156.5628, -328.3919) -> (-109.7259, -328.3919)
  curve K43 (-108.2848, -285.5182) -> (-156.5628, -328.3919)
  curve K44 (-109.7259, -328.3919) -> (-108.2848, -285.5182)
  line L31 (-174.2167, -328.3919) -> (-189.7089, -328.3919)
  curve K45 (-131.3429, -291.643) -> (-174.2167, -328.3919)
  curve K46 (-152.9599, -261.3791) -> (-131.3429, -291.643)
  curve K47 (-189.7089, -328.3919) -> (-152.9599, -261.3791)
  curve K48 (-78.5994, -104.6557) -> (-22.3952, -128.4345)
  curve K49 (-42.2108, -42.6869) -> (-78.5994, -104.6557)
  line L32 (-22.3952, -42.6869) -> (-42.2108, -42.6869)
  line L33 (-22.3952, -128.4345) -> (-22.3952, -42.6869)
  curve K50 (-84.1457, -106.4572) -> (-135.306, -170.8275)
  curve K51 (-132.784, -67.1862) -> (-84.1457, -106.4572)
  curve K52 (-145.7543, -130.9565) -> (-132.784, -67.1862)
  curve K53 (-135.306, -170.8275) -> (-145.7543, -130.9565)
  curve K54 (-93.5131, -42.6869) -> (-119.0933, -53.1352)
  line L34 (-56.4039, -42.6869) -> (-93.5131, -42.6869)
  curve K55 (-84.1457, -82.3182) -> (-56.4039, -42.6869)
  curve K56 (-119.0933, -53.1352) -> (-84.1457, -82.3182)
  curve K57 (-152.9599, -238.9426) -> (-152.9599, -238.9426)
  line L35 (0, -350) -> (0, 0)
  curve K58 (108.2848, -285.5182) -> (156.5628, -328.3919)
  curve K59 (109.7259, -328.3919) -> (108.2848, -285.5182)
  line L36 (156.5628, -328.3919) -> (109.7259, -328.3919)
  curve K60 (131.3429, -291.643) -> (174.2167, -328.3919)
  line L37 (174.2167, -328.3919) -> (189.7089, -328.3919)
  curve K61 (189.7089, -328.3919) -> (152.9599, -261.3791)
  curve K62 (152.9599, -261.3791) -> (131.3429, -291.643)
  curve K63 (152.9599, -238.9426) -> (152.9599, -238.9426)
  curve K64 (-153.8601, -238.4405) -> (-152.0598, -239.4447)
  curve K65 (153.8601, -238.4405) -> (152.0598, -239.4447)
  curve K66 (84.1457, -106.4572) -> (135.306, -170.8275)
  curve K67 (135.306, -170.8275) -> (145.7543, -130.9565)
  curve K68 (145.7543, -130.9565) -> (132.784, -67.1862)
  curve K69 (132.784, -67.1862) -> (84.1457, -106.4572)
  curve K70 (119.0933, -53.1352) -> (84.1457, -82.3182)
  curve K71 (93.5131, -42.6869) -> (119.0933, -53.1352)
  line L38 (56.4039, -42.6869) -> (93.5131, -42.6869)
  curve K72 (84.1457, -82.3182) -> (56.4039, -42.6869)
  curve K73 (42.2108, -42.6869) -> (78.5994, -104.6557)
  line L39 (22.3952, -42.6869) -> (42.2108, -42.6869)
  line L40 (22.3952, -128.4345) -> (22.3952, -42.6869)
  curve K74 (78.5994, -104.6557) -> (22.3952, -128.4345)
  point P1 (0, 0)
  point P96 (0, 0)
  point P92 (-152.9599, -238.9426)
  point P73 (-109.7259, -328.3919)
  point P100 (109.7259, -328.3919)
  point P74 (-156.5628, -328.3919)
  point P98 (156.5628, -328.3919)
  point P75 (-108.2848, -285.5182)
  point P99 (108.2848, -285.5182)
  point P76 (-189.7089, -328.3919)
  point P103 (189.7089, -328.3919)
  point P77 (-174.2167, -328.3919)
  point P101 (174.2167, -328.3919)
  point P78 (-131.3429, -291.643)
  point P102 (131.3429, -291.643)
  point P79 (-152.9599, -261.3791)
  point P104 (152.9599, -261.3791)
  point P80 (-22.3952, -128.4345)
  point P124 (22.3952, -128.4345)
  point P81 (-78.5994, -104.6557)
  point P121 (78.5994, -104.6557)
  point P82 (-42.2108, -42.6869)
  point P122 (42.2108, -42.6869)
  point P83 (-22.3952, -42.6869)
  point P123 (22.3952, -42.6869)
  point P84 (-135.306, -170.8275)
  point P113 (135.306, -170.8275)
  point P85 (-84.1457, -106.4572)
  point P114 (84.1457, -106.4572)
  point P86 (-132.784, -67.1862)
  point P116 (132.784, -67.1862)
  point P87 (-145.7543, -130.9565)
  point P115 (145.7543, -130.9565)
  point P88 (-119.0933, -53.1352)
  point P118 (119.0933, -53.1352)
  point P89 (-93.5131, -42.6869)
  point P119 (93.5131, -42.6869)
  point P90 (-56.4039, -42.6869)
  point P120 (56.4039, -42.6869)
  point P91 (-84.1457, -82.3182)
  point P117 (84.1457, -82.3182)
  point P105 (152.9599, -238.9426)
  point P93 (-146.5396, -206.4167)
  point P106 (146.5396, -206.4167)
  point P94 (-145.5686, -184.0855)
  point P107 (145.5686, -184.0855)
  point P95 (-140, -215)
  point P108 (140, -215)
  point P109 (-152.0598, -239.4447)
  point P111 (152.0598, -239.4447)
  point P110 (-153.8601, -238.4405)
  point P112 (153.8601, -238.4405)
  coincident P1 P96
  perpendicular L4 L35
  midpoint P92 K64
  symmetric P73 L35 P100
  symmetric P74 L35 P98
  symmetric K43 L35 K58
  symmetric P75 L35 P99
  symmetric K44 L35 K59
  symmetric P76 L35 P103
  symmetric P77 L35 P101
  symmetric K45 L35 K60
  symmetric P78 L35 P102
  symmetric K46 L35 K62
  symmetric P79 L35 P104
  symmetric K47 L35 K61
  symmetric K48 L35 K74
  symmetric P80 L35 P124
  symmetric P81 L35 P121
  symmetric K49 L35 K73
  symmetric P82 L35 P122
  symmetric P83 L35 P123
  symmetric K50 L35 K66
  symmetric P84 L35 P113
  symmetric P85 L35 P114
  symmetric K51 L35 K69
  symmetric P86 L35 P116
  symmetric K52 L35 K68
  symmetric P87 L35 P115
  symmetric K53 L35 K67
  symmetric K54 L35 K71
  symmetric P88 L35 P118
  symmetric P89 L35 P119
  symmetric P90 L35 P120
  symmetric K55 L35 K72
  symmetric P91 L35 P117
  symmetric K56 L35 K70
  symmetric P92 L35 P105
  symmetric P93 L35 P106
  symmetric P94 L35 P107
  symmetric P95 L35 P108
  symmetric L35 P109 P111
  symmetric L35 P110 P112
extrude "Extrude17" cut sketch "Sketch14" profile of L30 K43 K44 L31 K45 K46 K47 K48 K49 L32 L33 K50 K51 K52 K53 K54 L34 K55 K56 K57 K58 K59 L36 K60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 against normal blind 3
sketch "Sketch16" plane through (0, 0, 0) normal (0, 0, 1) x axis (1, 0, 0)
  line L1 (1578.8, 200) -> (-250, 200)
  line L2 (1578.8, -1019.2) -> (1578.8, 200)
  line L3 (-250, -1019.2) -> (1578.8, -1019.2)
  line L4 (-250, 200) -> (-250, -1019.2)
  point P2 (-250, 200)
  point P5 (-250, -1019.2)
  point P3 (1578.8, 200)
  horizontal L1
  vertical L2
  horizontal L3
  vertical L4
  dimension "d75" distance P2 P5 = 1219.2 (= "4 ft")
  dimension "d76" distance P2 P3 = 1828.8 (= "6 ft")
move "Move18"
move "Move19"
move "Move20"
move "Move22"
move "Move23"
extrude "Extrude21" cut of existing geometry blind 75
component_from_bodies "Body->Comp9"
component_from_bodies "Body->Comp10"
component_from_bodies "Body->Comp11"
step "Arrange" sketch "Sketch16" AngleFromX 0 Priority 500 AngleFromX 0 Priority 500 AngleFromX 0 Priority 500 originOffsetX 0 originOffsetY 0 grainDirection 0 objectSpacing 6.35 frameWidth 10 placementClearance 10
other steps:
base_feature "Base Feature1" bodies "FINAL LEG 2"
base_feature "Base Feature1" bodies "FINAL LEG 1"
base_feature "Base Feature1" bodies "FINAL top"
base_feature "Base Feature4" bodies "leg 2"
base_feature "Base Feature3" bodies "leg 1"
create_component "CreateComponent10"
remove_body "RemoveBody9"
create_component "CreateComponent11"
remove_body "RemoveBody10"
create_component "CreateComponent12"
remove_body "RemoveBody11"
create_component "CreateComponent13"
create_component "CreateComponent1"
named bodies: "FINAL top", "test", "leg 1", "leg 2", "FINAL LEG 1", "FINAL LEG 2"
